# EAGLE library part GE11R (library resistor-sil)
SIL RESISTOR
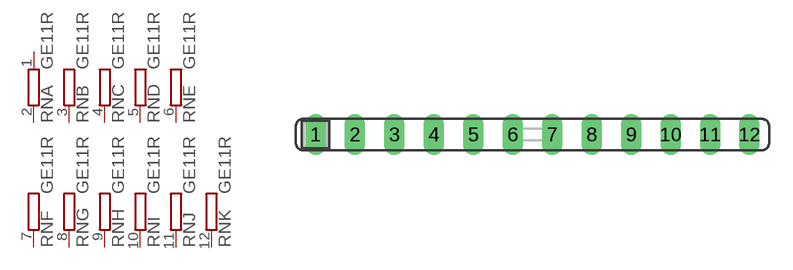
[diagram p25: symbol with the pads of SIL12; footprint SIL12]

Designator prefix RN; gates A=R-NV B=R-NV1 C=R-NV1 D=R-NV1 E=R-NV1 F=R-NV1 G=R-NV1 H=R-NV1 I=R-NV1 J=R-NV1 K=R-NV1

## GE11R (OC_FARNELL: unknown; OC_NEWARK: unknown)  [SIL12]
1  A:1  pas
2  A:2  pas
3  B:2  pas
4  C:2  pas
5  D:2  pas
6  E:2  pas
7  F:2  pas
8  G:2  pas
9  H:2  pas
10  I:2  pas
11  J:2  pas
12  K:2  pas

## Footprint SIL12 (pad centres in mm)
Single In Line
drill 0.813 long: 1 -13.97,0; 2 -11.43,0; 3 -8.89,0; 4 -6.35,0; 5 -3.81,0; 6 -1.27,0; 7 1.27,0; 8 3.81,0; 9 6.35,0; 10 8.89,0; 11 11.43,0; 12 13.97,0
